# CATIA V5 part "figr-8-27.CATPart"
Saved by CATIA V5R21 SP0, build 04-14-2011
Part number: Part2
Bounding box of the stored display mesh (mm): x -50 to 500, y -650 to 50, z 0 to 50
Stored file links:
  D:\CATIA V5R21 E-RESOURCES\CATIA-V5R21\catia-v5r21-prt\c08-catia-v5r20-prt\c08-catia-v5r21-figr-8-27.CATPart
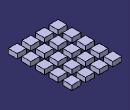
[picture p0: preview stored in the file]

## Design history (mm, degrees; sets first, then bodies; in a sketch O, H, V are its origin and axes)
Body1 (main body)
  Sketch1 on xy-plane, origin (0, 0, 0), H (1, 0, 0), V (0, 1, 0)
    line L1 (-50, 50) -> (50, 50)
    line L2 (50, 50) -> (50, -50)
    line L3 (50, -50) -> (-50, -50)
    line L4 (-50, -50) -> (-50, 50)
    axis line L5 (50, -50) -> (-50, 50)
    length L3 = 100
    length L2 = 100
    horizontal: L1 H, L3 H
    vertical: L2 V, L4 V
    midpoint: O L5
  Pad1: profile Sketch1, direction (0, 0, 1), length 50
  RectPattern1: of the body so far, direction 1 instances 4, spacing 150, along edge [face of Pad1 | face of Pad1], direction 2 instances 5, spacing 150, along edge [face of Pad1 | face of Pad1]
